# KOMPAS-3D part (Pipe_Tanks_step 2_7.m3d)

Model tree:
1. X Axis
2. Y Axis
3. Z Axis  (labels: T-Bend Dn 50; Pipe Dn 50)
     Òîëùèíà ñòåíêè 1 = 1

Referenced files in C:\Documents and Settings\kashirsky\Мои документы\Camtasia Studio\Pipelines3D\Tanks\: Tanks_step 2.a3d
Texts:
  Pipe Dn 50
  Steel ASTM A295
  Three Point Plane
  Plane at Angle
  Line and Point Plane
  Axis through Two Vertices
  Axis of Feature
  Axis of Conical Surface
  Axis through Edge
  Trim by Surface
  Trim by Sketch
  Feature with No History
  Intersection Axis of Two Planes
  Two Line Plane
  Line and Face Plane
  Bend by line
  Hole in sheet body
  Cut in sheet body
  Point in CM
  Linear Dimension from Line to Point
  Surface Finish Symbol
  Geometric Tolerance Symbol
  Leader #1
  Leader #2
  Leader #3
  Shape Deviations and Datum
  Node point number
  Mark of coordination axis
  Node point designation
  Mark/Reference designation with leader
  Mark/reference designation on line
  Mark/Reference designation without leader
  T-Bend Dn 50
  Plane of section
